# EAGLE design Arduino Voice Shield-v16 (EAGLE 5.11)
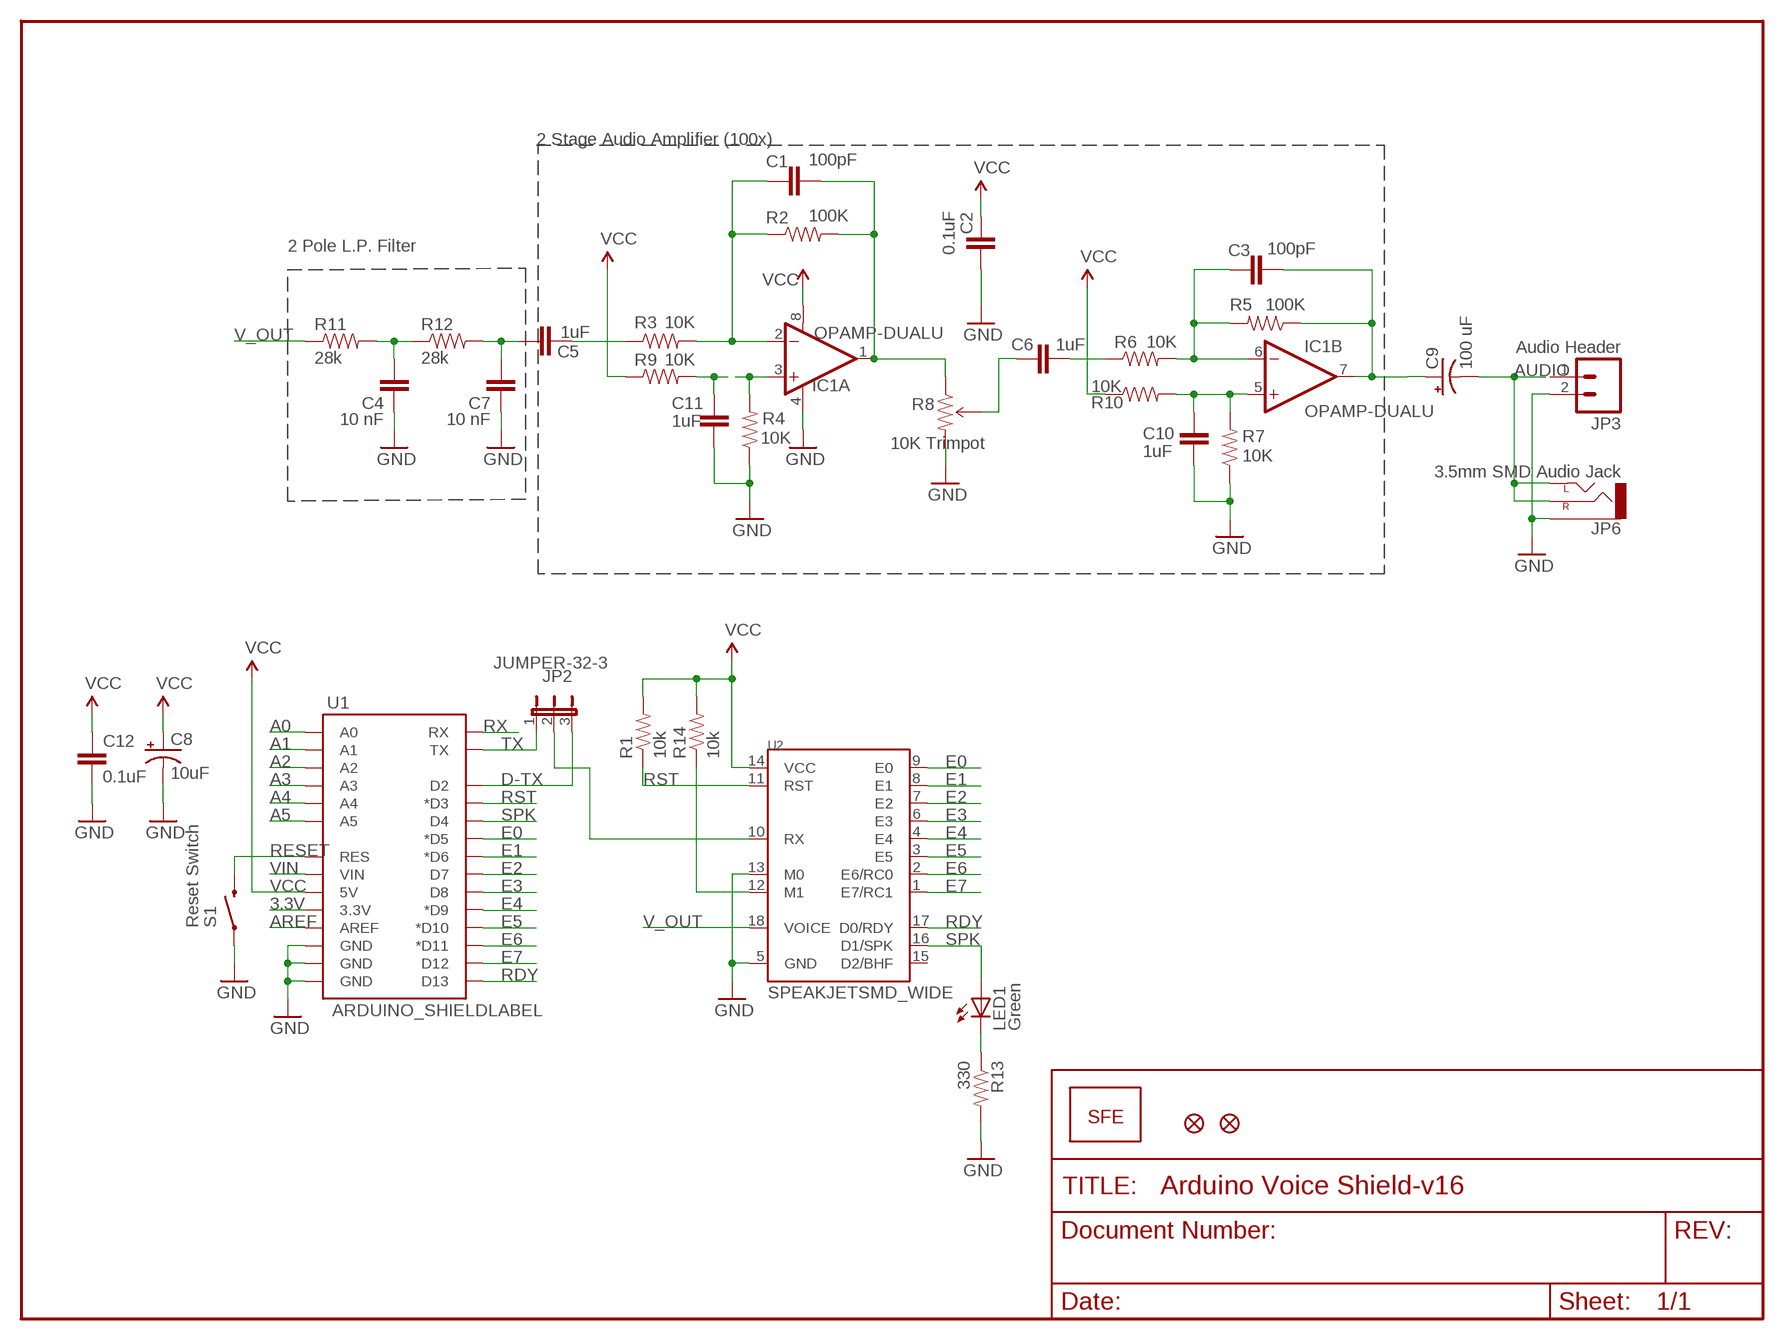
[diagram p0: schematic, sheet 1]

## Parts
C1  100pF  CAP0603-CAP  [0603-CAP]
C2  0.1uF  CAP0603-CAP  [0603-CAP]
C3  100pF  CAP0603-CAP  [0603-CAP]
C4  10 nF  CAP0603-CAP  [0603-CAP]
C5  1uF  CAP0603-CAP  [0603-CAP]
C6  1uF  CAP0603-CAP  [0603-CAP]
C7  10 nF  CAP0603-CAP  [0603-CAP]
C8  10uF  CAP_POL1206  [EIA3216]
C9  100 uF  CAP_POL7343  [EIA7343]
C10  1uF  CAP0603-CAP  [0603-CAP]
C11  1uF  CAP0603-CAP  [0603-CAP]
C12  0.1uF  CAP0603-CAP  [0603-CAP]
IC1  OPAMP-DUALU  [SO08]
JP1  LOGO-SFENEW  [SFE-NEW-WEBLOGO]
JP2  JUMPER-32-3  [SJ_3_PASTE2&3]
JP3  Audio Header  M02PTH  [1X02]
JP4  FIDUCIAL1X2  [FIDUCIAL-1X2]
JP5  FIDUCIAL1X2  [FIDUCIAL-1X2]
JP6  3.5mm SMD Audio Jack  AUDIO-JACKSMD2  [AUDIO-JACK-3.5MM-SMD]
LED1  Green  LED0603  [LED-0603]
R1  10k  RESISTOR0603-RES  [0603-RES]
R2  100K  RESISTOR0603-RES  [0603-RES]
R3  10K  RESISTOR0603-RES  [0603-RES]
R4  10K  RESISTOR0603-RES  [0603-RES]
R5  100K  RESISTOR0603-RES  [0603-RES]
R6  10K  RESISTOR0603-RES  [0603-RES]
R7  10K  RESISTOR0603-RES  [0603-RES]
R8  10K Trimpot  TRIMPOTSMD  [TRIMPOT-3MM]
R9  10K  RESISTOR0603  [0603]
R10  10K  RESISTOR0603  [0603]
R11  28k  RESISTOR0603-RES  [0603-RES]
R12  28k  RESISTOR0603-RES  [0603-RES]
R13  330  RESISTOR0603-RES  [0603-RES]
R14  10k  RESISTOR0603-RES  [0603-RES]
S1  Reset Switch  SWITCH-MOMENTARY-2SMD  [TACTILE_SWITCH_SMD]
U1  ARDUINO_SHIELDLABEL  [DUEMILANOVE_SHIELD]
U2  SPEAKJETSMD_WIDE  [SO-18W]

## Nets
3.3V: U1.3.3V
A0: U1.A0
A1: U1.A1
A2: U1.A2
A3: U1.A3
A4: U1.A4
A5: U1.A5
AREF: U1.AREF
AUDIO: C9.C(-) JP3.1 JP6.RING(RIGHT) JP6.TIP(LEFT)
D-TX: JP2.3 U1.D2
E0: U1.D5(*D5) U2.9(E0)
E1: U1.D6(*D6) U2.8(E1)
E2: U1.D7 U2.7(E2)
E3: U1.D8 U2.6(E3)
E4: U1.D9(*D9) U2.4(E4)
E5: U1.D10(*D10) U2.3(E5)
E6: U1.D11(*D11) U2.2(E6/RC0)
E7: U1.D12 U2.1(E7/RC1)
GND: C2.2 C4.1 C7.1 C8.C(-) C10.2 C11.2 C12.2 IC1.4(A:V-) JP3.2 JP6.SLEEVE R4.1 R7.1 R8.3(CW) R13.2 S1.1 U1.GND@0(GND) U1.GND@1(GND) U1.GND@2(GND) U2.5(GND) U2.13(M0)
IN1: C5.2 R3.1
N$3: JP2.2 U2.10(RX)
N$4: C1.1 IC1.2(A:-IN) R2.1 R3.2
N$5: C6.1 R6.1
N$6: C6.2 R8.2(WIPER)
N$7: C3.1 IC1.6(B:-IN) R5.2 R6.2
N$8: C10.1 IC1.5(B:+IN) R7.2 R10.2
N$9: C11.1 IC1.3(A:+IN) R4.2 R9.2
N$10: C4.2 R11.2 R12.1
N$11: C5.1 C7.2 R12.2
N$13: LED1.C R13.1
N$15: R14.1 U2.12(M1)
OUT1: C1.2 IC1.1(A:OUT) R2.2 R8.1(CCW)
RDY: U1.D13 U2.17(D0/RDY)
RESET: S1.3 U1.RES
RST: R1.1 U1.D3(*D3) U2.11(RST)
RX: U1.RX
SPK: LED1.A U1.D4 U2.16(D1/SPK)
SPK+: C3.2 C9.A(+) IC1.7(B:OUT) R5.1
TX: JP2.1 U1.TX
V_OUT: R11.1 U2.18(VOICE)
VCC: C2.1 C8.A(+) C12.1 IC1.8(A:V+) R1.2 R9.1 R10.1 R14.2 U1.5V U2.14(VCC)
VIN: U1.VIN
Unconnected: U2.15(D2/BHF)

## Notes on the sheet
- 2 Stage Audio Amplifier (100x)
- 2 Pole L.P. Filter

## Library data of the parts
C1-C7 C10-C12 = SparkFun:CAP: Capacitor
C8 C9 = SparkFun:CAP_POL: Capacitor Polarized
IC1 = SparkFun:OPAMP-DUAL: Operational Amplifier
JP1 = SparkFun:LOGO-SFE: Spark Fun Electronics PCB Logo
JP2 = SparkFun:JUMPER-3
JP3 = SparkFun:M02: Header 2
JP4 JP5 = SparkFun:FIDUCIAL: Fiducial Alignment Points
JP6 = SparkFun:AUDIO-JACK: 3.5mm Audio Jack Simple 3.5mm common PCB mount audio jack. SKU: PRT-08032
LED1 = SparkFun:LED: LEDs
R1-R7 R11-R14 = SparkFun:RESISTOR: Resistor
R8 = SparkFun:TRIMPOT
R9 R10 = SparkFun-DC:RESISTOR: Resistor
S1 = SparkFun:SWITCH-MOMENTARY-2
U1 = SparkFun:ARDUINO_SHIELD
U2 = SparkFun:SPEAKJET

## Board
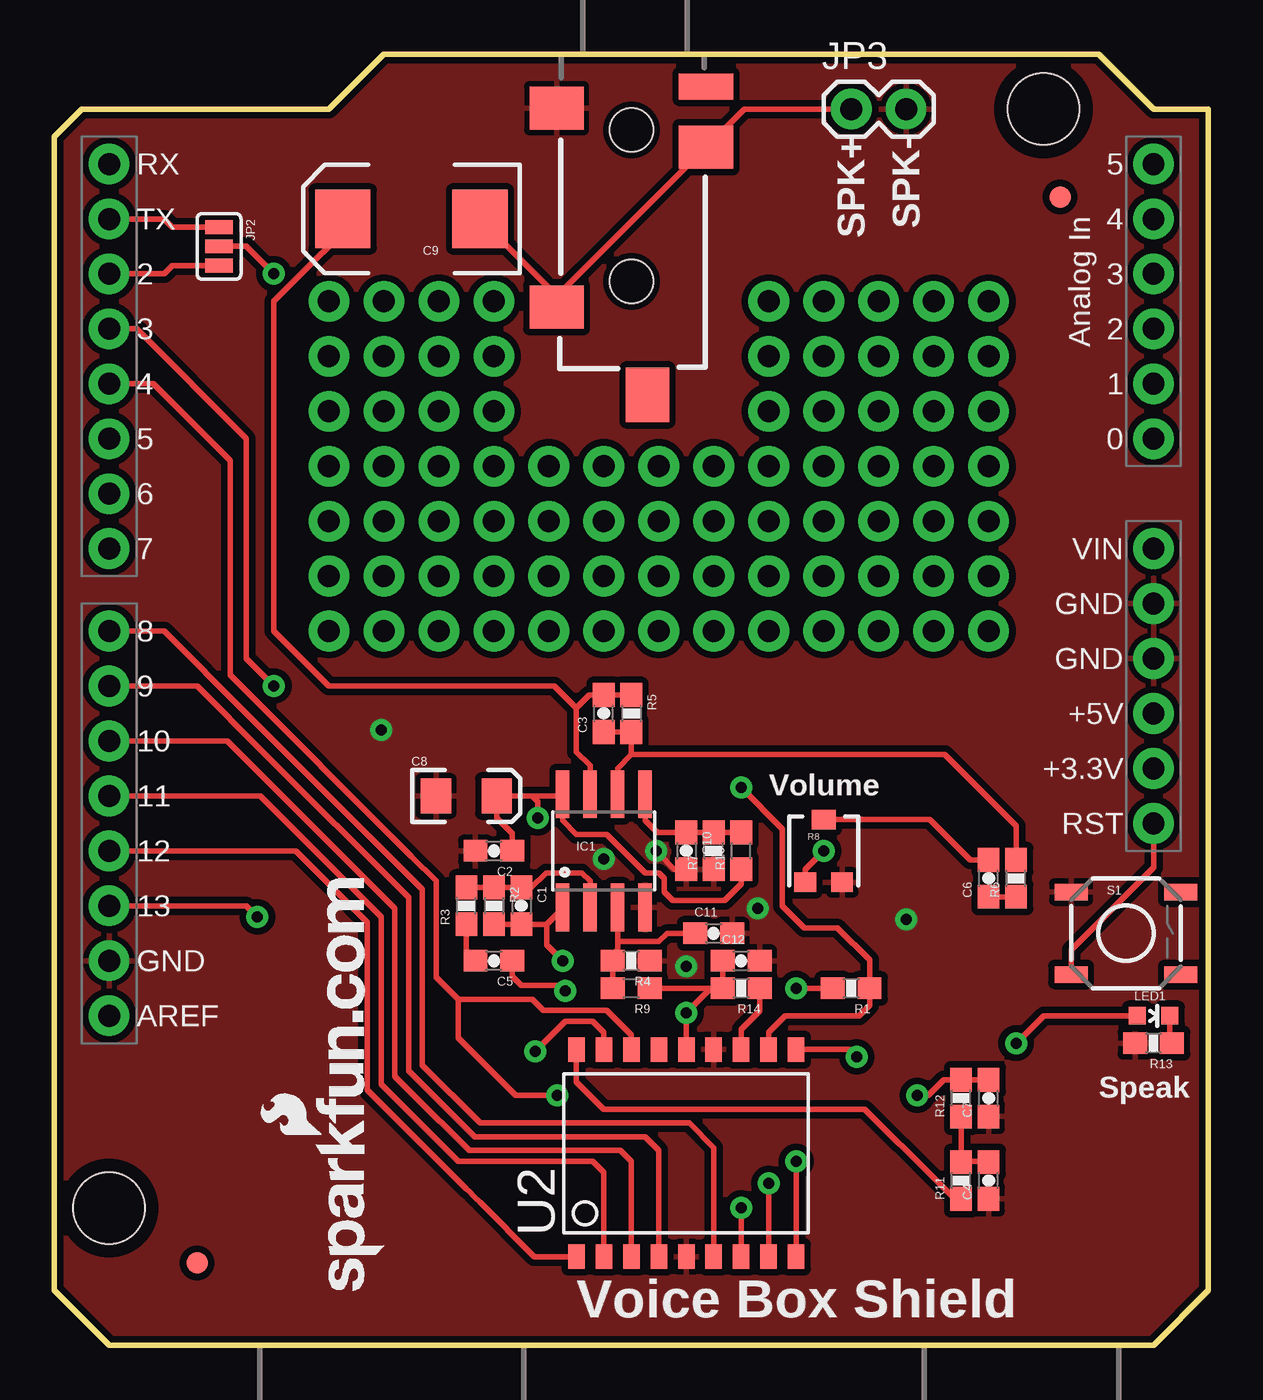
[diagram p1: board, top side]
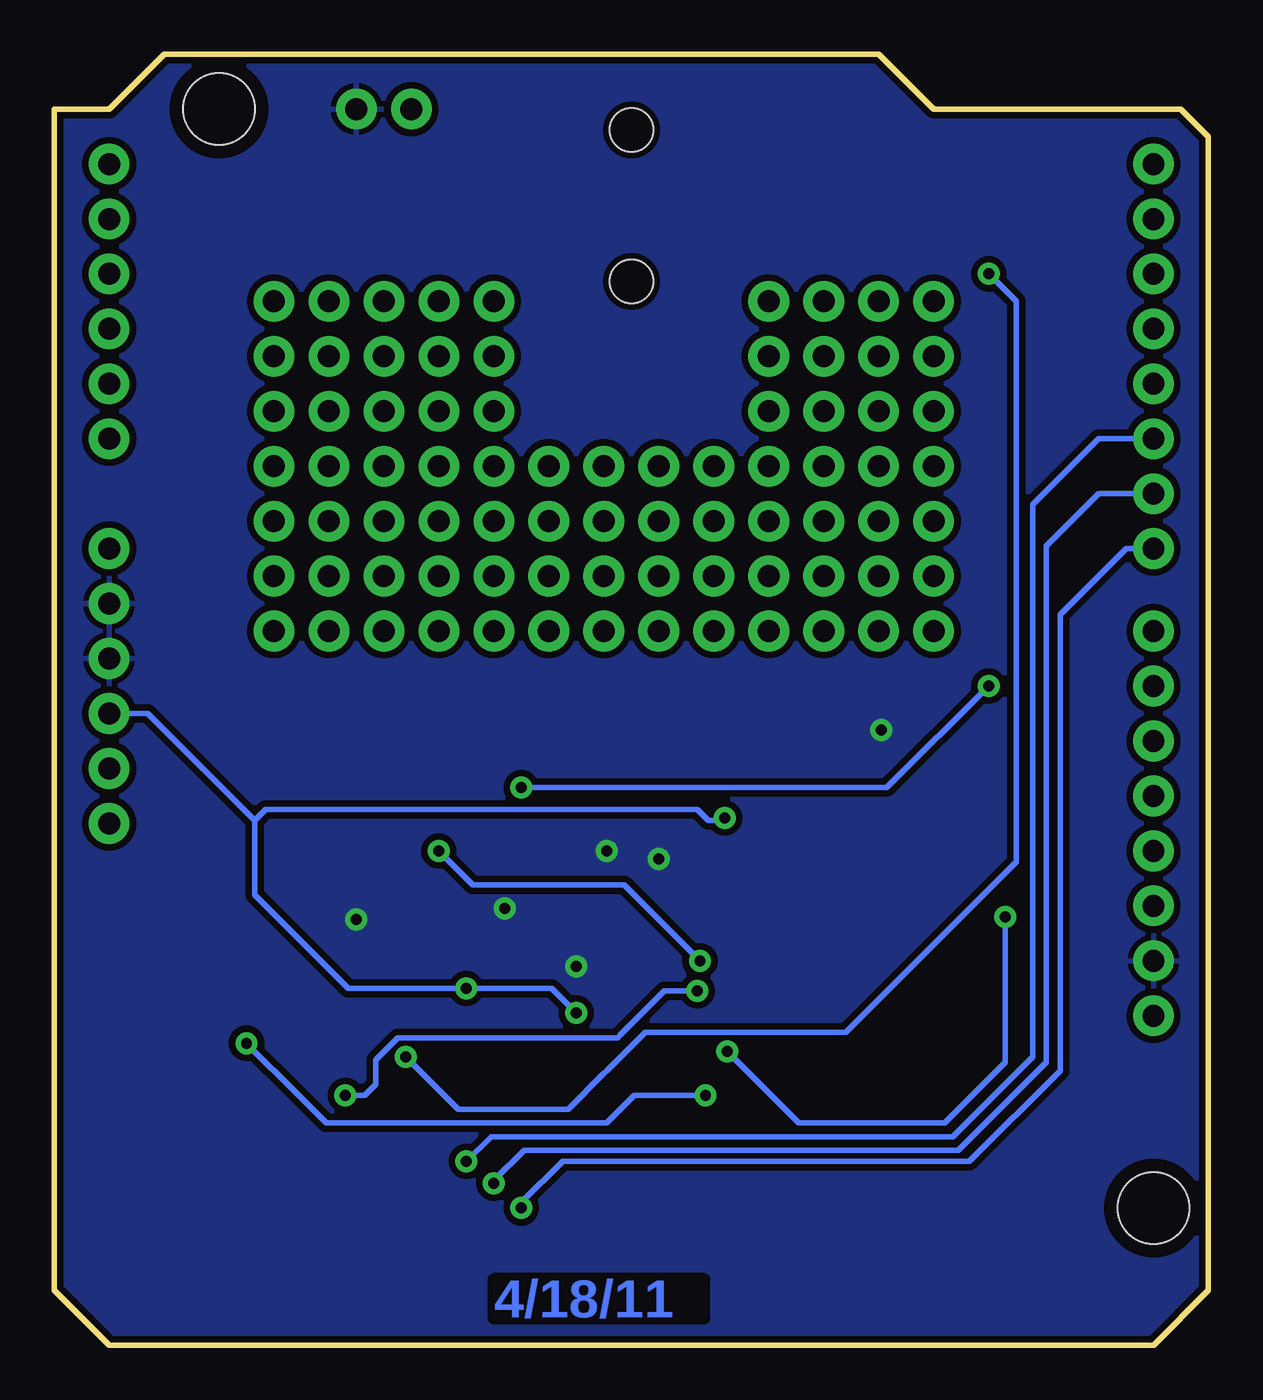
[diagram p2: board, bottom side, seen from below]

Size 53.34 x 59.69 mm. Coordinates in mm from the lower left corner, seen from the top.
Outline: 2.54,0 0,2.54 0,55.88 1.27,57.15 12.7,57.15 15.24,59.69 48.26,59.69 50.8,57.15 53.34,57.15 53.34,2.54 50.8,0 2.54,0
Copper layers (1*16): Top 0.035mm / dielectric 1.5mm / Bottom 0.035mm
Design rules "SparkFun *": minimum track width 8mil, minimum drill 20mil, track to track 8mil, track to pad 8mil, pad to pad 8mil, via to via 8mil, smd to smd 8mil, copper to edge 9mil, drill to drill 8mil, minimum pad ring 12mil, minimum via ring 10mil, stop-mask expansion 4mil, vias tented up to drill 20mil, thermal gap 10mil

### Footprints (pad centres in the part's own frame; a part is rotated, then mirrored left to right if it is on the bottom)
0603-CAP = smd 1.1 x 1: 1 -0.85,0; 2 0.85,0
EIA3216 = smd 1.4 x 1.6: A 1.4,0; C -1.4,0
EIA7343 = smd 2.55 x 2.7: A 3.17,0; C -3.17,0
SO08 = smd 0.61 x 2.21: 1 -1.905,-2.616; 2 -0.635,-2.616; 3 0.635,-2.616; 4 1.905,-2.616; 5 1.905,2.616; 6 0.635,2.616; 7 -0.635,2.616; 8 -1.905,2.616
SJ_3_PASTE2&3 = smd 0.635 x 1.27: 1 -0.889,0; 2 0,0; 3 0.889,0
1X02 = drill 1.016 pad 1.88 round: 1 0,0; 2 2.54,0
FIDUCIAL-1X2 = smd 1 x 1: 1 0,0
AUDIO-JACK-3.5MM-SMD = smd 2 x 2.5: RING 4.3,3.45; SLEEVE 2.5,-3.45; TIP 11.7,-3.45 | smd 1.2 x 2.5: RSH 1.5,3.45 | smd 2.5 x 2: TSH 15.75,0.75 | hole 2: 3.5,0; 10.5,0
LED-0603 = smd 0.8 x 0.8: A 0,-0.75; C 0,0.75
0603-RES = smd 1.1 x 1: 1 -0.85,0; 2 0.85,0
TRIMPOT-3MM = smd 1 x 0.9: 1 -0.85,-1.45; 3 0.85,-1.45 | smd 1.1 x 0.9: 2 0,1.45
0603 = smd 1.1 x 1: 1 -0.85,0; 2 0.85,0
TACTILE_SWITCH_SMD = smd 1.524 x 0.762: 1 -2.54,1.905; 2 2.54,1.905; 3 -2.54,-1.905; 4 2.54,-1.905
DUEMILANOVE_SHIELD = drill 1.016 pad 1.88 round: 3.3V 50.8,26.67; 5V 50.8,29.21; A0 50.8,41.91; A1 50.8,44.45; A2 50.8,46.99; A3 50.8,49.53; A4 50.8,52.07; A5 50.8,54.61; AREF 2.54,15.24; D2 2.54,49.53; D3 2.54,46.99; D4 2.54,44.45; D5 2.54,41.91; D6 2.54,39.37; D7 2.54,36.83; D8 2.54,33.02; D9 2.54,30.48; D10 2.54,27.94; D11 2.54,25.4; D12 2.54,22.86; D13 2.54,20.32; GND@0 50.8,31.75; GND@1 50.8,34.29; GND@2 2.54,17.78; RES 50.8,24.13; RX 2.54,54.61; TX 2.54,52.07; VIN 50.8,36.83 | hole 3.302: 45.72,57.15; 2.54,6.35
SO-18W = smd 0.762 x 1.143: 1 -5.08,-4.788; 2 -3.81,-4.788; 3 -2.54,-4.788; 4 -1.27,-4.788; 5 0,-4.788; 6 1.27,-4.788; 7 2.54,-4.788; 8 3.81,-4.788; 9 5.08,-4.788; 10 5.08,4.788; 11 3.81,4.788; 12 2.54,4.788; 13 1.27,4.788; 14 0,4.788; 15 -1.27,4.788; 16 -2.54,4.788; 17 -3.81,4.788; 18 -5.08,4.788

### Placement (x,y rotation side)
C1  21.59,20.32 270 top
C2  20.32,22.86 180 top
C3  25.4,29.21 90 top
C4  43.18,7.62 90 top
C5  20.32,17.78 180 top
C6  43.18,21.59 90 top
C7  43.18,11.43 90 top
C8  19.05,25.4 0 top
C9  16.51,52.07 180 top
C10  29.21,22.86 270 top
C11  30.48,19.05 0 top
C12  31.75,17.78 0 top
IC1  25.4,22.86 0 top
JP1  15.24,2.54 90 top
JP2  7.62,50.8 270 top
JP3  36.83,57.15 0 top
JP4  46.48,53.09 0 top
JP5  6.6,3.81 0 top
JP6  26.67,59.69 270 top
LED1  50.8,15.24 270 top
R1  36.83,16.51 180 top
R2  20.32,20.32 270 top
R3  19.05,20.32 90 top
R4  26.67,17.78 180 top
R5  26.67,29.21 270 top
R6  44.45,21.59 90 top
R7  30.48,22.86 90 top
R8  35.56,22.86 0 top
R9  26.67,16.51 180 top
R10  31.75,22.86 90 top
R11  41.91,7.62 90 top
R12  41.91,11.43 90 top
R13  50.8,13.97 180 top
R14  31.75,16.51 180 top
S1  49.53,19.05 0 top
U1  0,0 0 top
U2  29.21,8.89 0 top

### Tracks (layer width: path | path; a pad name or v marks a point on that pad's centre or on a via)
AUDIO
  Top 0.254: 22.95,48.26 22.86,48.26 | 22.95,48.26 JP6.TIP 22.95,48.26 | C9.C 22.86,48.89 22.86,48.26 | 22.95,48.26 22.86,48.26 | 22.86,48.26 22.99,48.26 JP6.RING 31.88,57.15 JP3.1
D-TX
  Top 0.254: U1.D2 5.08,49.53 5.46,49.91 JP2.3
E0  (via drill 0.51)
  Top 0.254: v34.29,8.51 U2.9
  Bottom 0.254: U1.D5 5.08,41.91 8.13,38.86 8.13,28.7 8.13,19.68 8.13,13.34 11.81,9.65 31.11,9.65 31.88,9.65 32.38,9.65 33.15,9.65 v34.29,8.51
E1  (via drill 0.51)
  Top 0.254: v33.02,7.49 U2.8
  Bottom 0.254: U1.D6 5.08,39.37 7.49,36.96 7.49,26.8 7.49,17.65 7.49,13.08 11.56,9.02 30.35,9.02 31.11,9.02 31.62,9.02 33.02,7.62 v33.02,7.49
E2  (via drill 0.51)
  Top 0.254: v31.75,6.35 U2.7
  Bottom 0.254: U1.D7 3.81,36.83 6.86,33.78 6.86,24.89 6.86,16.13 6.86,12.7 11.05,8.51 29.59,8.51 29.84,8.51 31.75,6.6 v31.75,6.35
E3
  Top 0.254: U1.D8 5.08,33.02 8.89,29.21 17.02,21.08 17.02,13.59 17.02,12.95 19.68,10.29 28.32,10.29 28.57,10.29 29.08,10.29 29.34,10.29 30.48,9.14 U2.6
E4
  Top 0.254: U1.D9 6.6,30.48 9.65,27.43 16.38,20.7 16.38,17.27 16.38,12.7 17.65,11.43 19.43,9.65 20.95,9.65 23.88,9.65 27.05,9.65 27.3,9.65 27.94,9.02 U2.4
E5
  Top 0.254: U1.D10 8,27.94 9.14,26.8 15.75,20.19 15.75,17.4 15.75,12.45 16.51,11.68 19.18,9.02 21.84,9.02 23.11,9.02 26.04,9.02 26.16,9.02 26.67,8.51 U2.3
E6
  Top 0.254: U1.D11 9.53,25.4 10.67,24.26 15.11,19.81 15.11,16.51 15.11,12.06 16.38,10.79 18.67,8.51 20.45,8.51 20.7,8.51 24.26,8.51 24.77,8.51 24.89,8.51 25.4,8 U2.2
E7
  Top 0.254: U1.D12 11.18,22.86 12.19,21.84 14.48,19.56 14.48,17.65 14.48,11.81 16.13,10.16 19.05,7.24 19.18,7.11 19.41,6.88 19.68,6.6 22.19,4.1 U2.1
GND  (via drill 0.51)
  Top 0.254: v27.81,22.86 27.94,22.73 28.66,22.01 C10.2
  other vias: 25.4,22.48 32.51,20.19 29.21,17.53 39.37,19.68 15.11,28.45
  pour Bottom (isolate 0.305): 0,2.54 0,55.88 1.27,57.15 12.7,57.15 15.24,59.69 48.26,59.69 50.8,57.15 53.34,57.15 53.34,2.54 50.8,0 2.54,0
  pour Top (isolate 0.305): 0,2.54 0,55.88 1.27,57.15 12.7,57.15 15.24,59.69 48.26,59.69 50.8,57.15 53.34,57.15 53.34,2.54 50.8,0 2.54,0
IN1
  Top 0.254: C5.2 19.47,17.87 19.43,17.91 19.05,18.29 R3.1
N$3  (via drill 0.51)
  Top 0.254: JP2.2 8.89,50.8 v10.16,49.53 | 36.91,13.51 v37.08,13.34 36.83,13.59 36.74,13.68 U2.10
  Bottom 0.254: v10.16,49.53 8.89,48.26 8.89,44.96 8.89,22.35 14.73,16.51 16.76,14.48 21.59,14.48 26.04,14.48 27.81,12.7 27.94,12.57 29.59,10.92 34.29,10.92 34.67,10.92 v37.08,13.34
N$4
  Top 0.254: IC1.2 24.77,21.46 24.38,21.84 24.26,21.84 22.73,21.84 22.06,21.17 C1.1 21.5,21.17 21.46,21.21 21.42,21.17 R2.1 20.32,21.21 20.28,21.17 R3.2
N$5
  Top 0.254: R6.1 44.23,20.74 44.2,20.7 44.16,20.74 C6.1
N$6
  Top 0.254: R8.2 40.46,24.31 41.91,22.86 42.33,22.44 C6.2
N$7
  Top 0.254: IC1.6 26.04,26.67 26.67,27.3 | 26.67,28.32 R5.2 26.67,28.32 | 26.67,27.3 26.67,28.32 | C3.1 26.63,28.36 26.67,28.32 | R6.2 44.45,24 41.15,27.3 26.8,27.3 26.67,27.3
N$8
  Top 0.254: R10.2 31.54,23.71 31.5,23.75 31.46,23.71 R7.2 30.31,23.71 30.23,23.62 30.14,23.71 C10.1 27.85,23.71 27.81,23.75 27.3,24.26 IC1.5
N$9
  Top 0.254: 26.04,18.67 26.04,18.29 25.78,18.03 25.82,18 R4.2 26.04,17.78 25.82,17.57 R9.2 | 26.04,18.67 IC1.3 | C11.1 28.32,19.05 27.94,18.67 26.04,18.67
N$10
  Top 0.254: R11.2 41.91,8.51 | 41.91,8.51 R12.1 | C4.2 42.97,8.47 42.93,8.51 41.91,8.51
N$11  (via drill 0.51)
  Top 0.254: C7.2 42.2,12.28 42.16,12.32 42.12,12.28 R12.2 41.11,12.28 41.02,12.19 40.39,11.56 v39.88,11.56 | C5.1 21.17,17.06 21.59,16.64 23.37,16.64 v23.62,16.38
  Bottom 0.254: v39.88,11.56 38.99,11.56 38.48,12.06 38.48,13.21 37.47,14.22 27.3,14.22 27.18,14.35 25.15,16.38 v23.62,16.38
N$13
  Top 0.254: R13.1 51.65,14.01 51.56,14.1 51.55,14.11 LED1.C
N$15
  Top 0.254: U2.12 31.75,14.61 32.51,15.37 32.6,15.46 R14.1
N$16  (via drill 1.02 pad 1.88)
  other vias: 12.7,33.02
N$17  (via drill 1.02 pad 1.88)
  other vias: 15.24,33.02
N$18  (via drill 1.02 pad 1.88)
  other vias: 17.78,33.02
N$19  (via drill 1.02 pad 1.88)
  other vias: 20.32,33.02
N$20  (via drill 1.02 pad 1.88)
  other vias: 22.86,33.02
N$21  (via drill 1.02 pad 1.88)
  other vias: 27.94,33.02
N$22  (via drill 1.02 pad 1.88)
  other vias: 30.48,33.02
N$23  (via drill 1.02 pad 1.88)
  other vias: 33.02,33.02
N$24  (via drill 1.02 pad 1.88)
  other vias: 35.56,33.02
N$25  (via drill 1.02 pad 1.88)
  other vias: 38.1,33.02
N$26  (via drill 1.02 pad 1.88)
  other vias: 40.64,33.02
N$27  (via drill 1.02 pad 1.88)
  other vias: 43.18,33.02
N$28  (via drill 1.02 pad 1.88)
  other vias: 43.18,35.56
N$29  (via drill 1.02 pad 1.88)
  other vias: 40.64,35.56
N$30  (via drill 1.02 pad 1.88)
  other vias: 38.1,35.56
N$31  (via drill 1.02 pad 1.88)
  other vias: 35.56,35.56
N$32  (via drill 1.02 pad 1.88)
  other vias: 33.02,35.56
N$33  (via drill 1.02 pad 1.88)
  other vias: 30.48,35.56
N$34  (via drill 1.02 pad 1.88)
  other vias: 27.94,35.56
N$35  (via drill 1.02 pad 1.88)
  other vias: 25.4,35.56
N$36  (via drill 1.02 pad 1.88)
  other vias: 22.86,35.56
N$37  (via drill 1.02 pad 1.88)
  other vias: 20.32,35.56
N$38  (via drill 1.02 pad 1.88)
  other vias: 17.78,35.56
N$39  (via drill 1.02 pad 1.88)
  other vias: 15.24,35.56
N$40  (via drill 1.02 pad 1.88)
  other vias: 12.7,35.56
N$41  (via drill 1.02 pad 1.88)
  other vias: 12.7,38.1
N$42  (via drill 1.02 pad 1.88)
  other vias: 15.24,38.1
N$43  (via drill 1.02 pad 1.88)
  other vias: 17.78,38.1
N$44  (via drill 1.02 pad 1.88)
  other vias: 20.32,38.1
N$45  (via drill 1.02 pad 1.88)
  other vias: 22.86,38.1
N$46  (via drill 1.02 pad 1.88)
  other vias: 25.4,38.1
N$47  (via drill 1.02 pad 1.88)
  other vias: 27.94,38.1
N$48  (via drill 1.02 pad 1.88)
  other vias: 30.48,38.1
N$49  (via drill 1.02 pad 1.88)
  other vias: 33.02,38.1
N$50  (via drill 1.02 pad 1.88)
  other vias: 35.56,38.1
N$51  (via drill 1.02 pad 1.88)
  other vias: 38.1,38.1
N$52  (via drill 1.02 pad 1.88)
  other vias: 40.64,38.1
N$53  (via drill 1.02 pad 1.88)
  other vias: 43.18,38.1
N$54  (via drill 1.02 pad 1.88)
  other vias: 43.18,40.64
N$55  (via drill 1.02 pad 1.88)
  other vias: 40.64,40.64
N$56  (via drill 1.02 pad 1.88)
  other vias: 38.1,40.64
N$57  (via drill 1.02 pad 1.88)
  other vias: 35.56,40.64
N$58  (via drill 1.02 pad 1.88)
  other vias: 33.02,40.64
N$59  (via drill 1.02 pad 1.88)
  other vias: 30.48,40.64
N$60  (via drill 1.02 pad 1.88)
  other vias: 27.94,40.64
N$61  (via drill 1.02 pad 1.88)
  other vias: 25.4,40.64
N$62  (via drill 1.02 pad 1.88)
  other vias: 22.86,40.64
N$63  (via drill 1.02 pad 1.88)
  other vias: 20.32,40.64
N$64  (via drill 1.02 pad 1.88)
  other vias: 17.78,40.64
N$65  (via drill 1.02 pad 1.88)
  other vias: 15.24,40.64
N$66  (via drill 1.02 pad 1.88)
  other vias: 12.7,40.64
N$67  (via drill 1.02 pad 1.88)
  other vias: 12.7,43.18
N$68  (via drill 1.02 pad 1.88)
  other vias: 15.24,43.18
N$69  (via drill 1.02 pad 1.88)
  other vias: 17.78,43.18
N$70  (via drill 1.02 pad 1.88)
  other vias: 20.32,43.18
N$75  (via drill 1.02 pad 1.88)
  other vias: 33.02,43.18
N$76  (via drill 1.02 pad 1.88)
  other vias: 35.56,43.18
N$77  (via drill 1.02 pad 1.88)
  other vias: 38.1,43.18
N$78  (via drill 1.02 pad 1.88)
  other vias: 40.64,43.18
N$79  (via drill 1.02 pad 1.88)
  other vias: 43.18,43.18
N$80  (via drill 1.02 pad 1.88)
  other vias: 43.18,45.72
N$81  (via drill 1.02 pad 1.88)
  other vias: 40.64,45.72
N$82  (via drill 1.02 pad 1.88)
  other vias: 38.1,45.72
N$83  (via drill 1.02 pad 1.88)
  other vias: 35.56,45.72
N$84  (via drill 1.02 pad 1.88)
  other vias: 33.02,45.72
N$89  (via drill 1.02 pad 1.88)
  other vias: 20.32,45.72
N$90  (via drill 1.02 pad 1.88)
  other vias: 17.78,45.72
N$91  (via drill 1.02 pad 1.88)
  other vias: 15.24,45.72
N$92  (via drill 1.02 pad 1.88)
  other vias: 12.7,45.72
N$93  (via drill 1.02 pad 1.88)
  other vias: 12.7,48.26
N$94  (via drill 1.02 pad 1.88)
  other vias: 17.78,48.26
N$95  (via drill 1.02 pad 1.88)
  other vias: 15.24,48.26
N$96  (via drill 1.02 pad 1.88)
  other vias: 20.32,48.26
N$101  (via drill 1.02 pad 1.88)
  other vias: 33.02,48.26
N$102  (via drill 1.02 pad 1.88)
  other vias: 35.56,48.26
N$103  (via drill 1.02 pad 1.88)
  other vias: 38.1,48.26
N$104  (via drill 1.02 pad 1.88)
  other vias: 40.64,48.26
N$105  (via drill 1.02 pad 1.88)
  other vias: 43.18,48.26
N$106  (via drill 1.02 pad 1.88)
  other vias: 25.4,33.02
OUT1  (via drill 0.51)
  Top 0.254: IC1.1 23.5,20.19 22.86,19.56 22.77,19.47 | 22.77,19.47 22.73,19.47 C1.2 21.59,19.43 21.55,19.47 R2.2 | 22.77,19.47 22.77,18.5 v23.5,17.78 | R8.1 34.71,22.01 v35.56,22.86
  Bottom 0.254: v23.5,17.78 27,21.29 33.98,21.29 v35.56,22.86
RDY  (via drill 0.51)
  Top 0.254: U1.D13 8.89,20.32 v9.4,19.81 | v22.23,13.59 23.62,14.99 24.26,14.99 24.51,14.99 24.89,14.99 25.4,14.48 U2.17
  Bottom 0.254: v9.4,19.81 9.4,13.08 10.92,11.56 12.19,10.29 13.34,10.29 18.03,10.29 18.92,10.29 v22.23,13.59
RESET
  Top 0.254: U1.RES 50.8,22.1 49.02,20.32 46.99,18.29 46.99,17.27 S1.3
RST  (via drill 0.51)
  Top 0.254: v31.75,25.78 33.66,23.88 33.66,20.32 34.67,19.3 36.2,19.3 37.68,17.82 R1.1 37.68,15.71 37.59,15.62 37.47,15.49 37.21,15.24 34.67,15.24 34.42,15.24 33.78,15.24 33.02,14.48 U2.11 | v10.16,30.48 8.89,31.75 8.89,33.27 8.89,41.91 3.81,46.99 U1.D3
  Bottom 0.254: v31.75,25.78 14.86,25.78 v10.16,30.48
SPK  (via drill 0.51)
  Top 0.254: 18.67,16 21.84,16 22.1,16 22.61,15.49 24.77,15.49 25.02,15.49 25.53,15.49 26.67,14.35 U2.16 | 18.67,16 17.65,17.02 17.65,21.46 16.51,22.61 8.13,30.99 8.13,36.7 8.13,40.89 4.57,44.45 4.32,44.45 U1.D4 | LED1.A 45.72,15.24 v44.45,13.97 | 18.67,16 18.67,14.22 21.34,11.56 v23.24,11.56
  Bottom 0.254: v44.45,13.97 42.04,11.56 40.77,10.29 28.45,10.29 27.81,10.29 26.54,11.56 v23.24,11.56
SPK+
  Top 0.254: IC1.7 24.77,26.8 24.13,27.43 24.13,27.69 24.13,29.46 | 24.13,29.46 24.73,30.06 C3.2 26.58,30.06 26.67,29.97 R5.1 | C9.A 13.34,51.44 11.43,49.53 10.16,48.26 10.16,46.99 10.16,33.02 11.43,31.75 12.7,30.48 16.51,30.48 23.11,30.48 24.13,29.46
TX
  Top 0.254: U1.TX 5.08,52.07 5.46,51.69 JP2.1
V_OUT
  Top 0.254: R11.1 41.62,6.77 41.02,7.37 40.77,7.62 37.47,10.92 37.34,10.92 36.96,10.92 26.29,10.92 26.16,10.92 25.4,10.92 24.13,12.19 U2.18
VCC  (via drill 0.51)
  Top 0.254: v34.29,16.51 R1.2 | R10.1 31.75,21.34 30.99,20.57 28.57,20.57 28.19,20.95 28.19,21.59 27.94,21.84 27.56,21.84 27.3,21.84 26.67,22.48 25.65,23.5 25.53,23.62 24.38,23.62 24.13,23.62 23.5,24.26 IC1.8 23.44,25.48 23.37,25.4 22.1,25.4 | 22.1,25.4 C8.A 20.45,24.38 20.57,24.26 21.17,23.66 C2.1 | C12.1 30.9,16.68 30.86,16.64 30.9,16.6 R14.2 30.86,16.51 | v22.35,24.38 22.35,25.15 22.1,25.4 | R9.1 30.86,16.51 | 30.86,16.51 30.35,16.51 v29.21,15.37 29.21,15.11 U2.14
  Bottom 0.254: U1.5V 49.02,29.21 44.07,24.26 | v22.35,24.38 22.48,24.26 23.11,24.26 23.62,24.77 43.56,24.77 44.07,24.26 | 44.07,24.26 44.07,24.13 44.07,20.83 39.75,16.51 v34.29,16.51 31.75,16.51 30.35,16.51 v29.21,15.37

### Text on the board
Bottom: 4/18/11
tPlace: SPK+ | SPK- | Volume | Speak | Voice Box Shield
